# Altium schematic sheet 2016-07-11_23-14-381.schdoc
size 344 x 125 mm; SheetNumber: 1; SheetTotal: 1
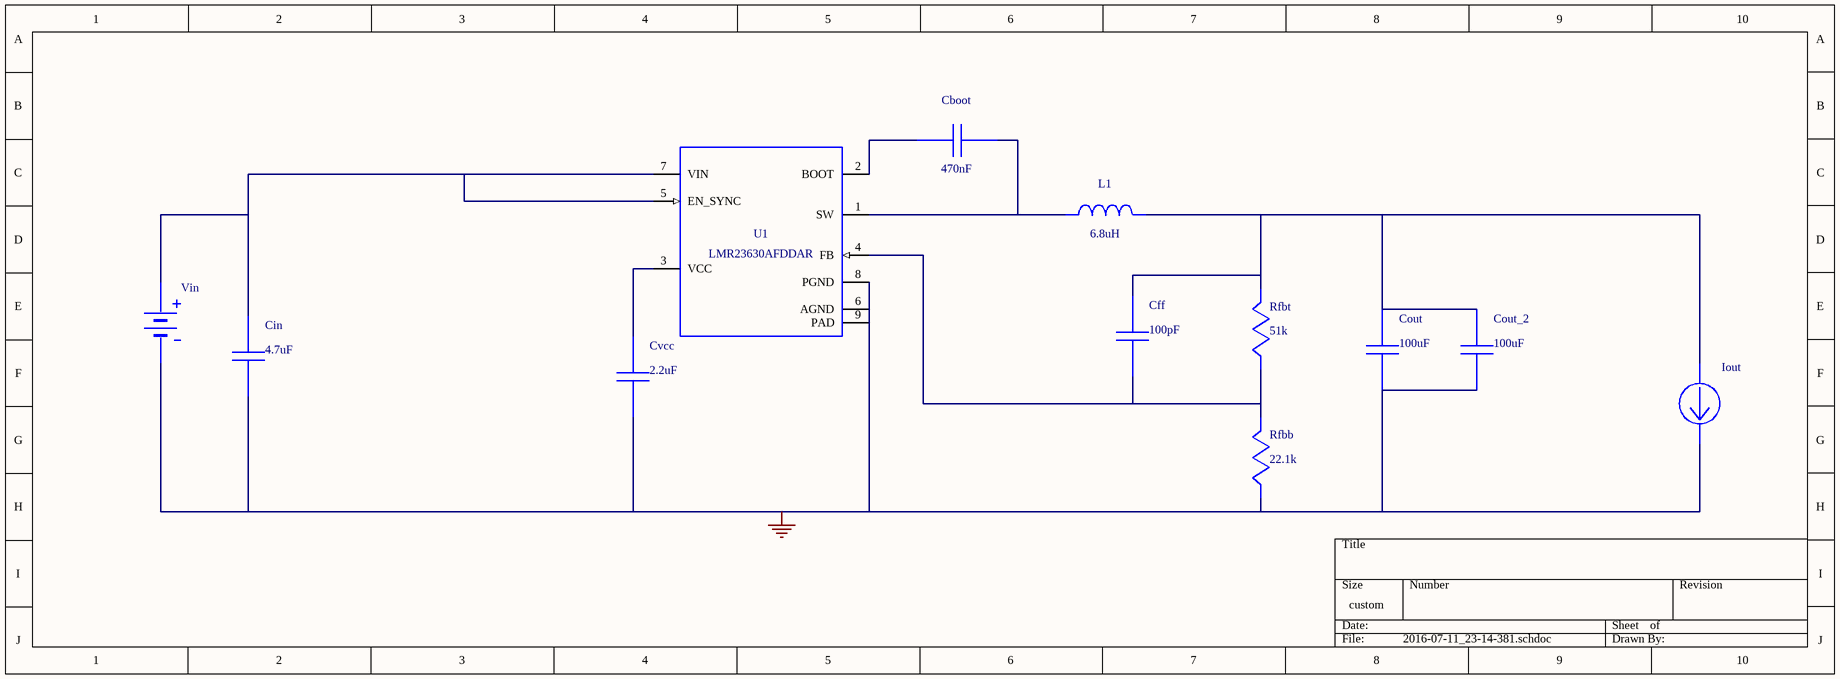
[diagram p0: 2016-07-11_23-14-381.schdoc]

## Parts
Cboot  value 470nF  (hidden comment: GRM21BR71H474KA88L)
Cff  value 100pF  (hidden comment: C0603C101J3GACTU)
Cin  value 4.7uF  (hidden comment: GRM31CR71H475KA12L)
Cout  value 100uF  (hidden comment: GRM31CR60J107ME39L)
Cout_2  value 100uF  (hidden comment: GRM31CR60J107ME39L)
Cvcc  value 2.2uF  (hidden comment: GRM188R60J225KE19D)
Iout  WB_CURRENT_LOAD  (value not drawn)
L1  value 6.8uH  (hidden comment: SRP6540-6R8M)
Rfbb  value 22.1k  (hidden comment: ERJ-6ENF2212V)
Rfbt  value 51k  (hidden comment: RC0603FR-0751KL)
U1  LMR23630AFDDAR
Vin  WB_BATTERY  (value not drawn)

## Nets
0: Cin.2 Cout.2 Cout_2.2 Cvcc.2 Iout.2(-) Rfbb.2 U1.6(AGND) U1.8(PGND) U1.9(PAD) Vin.2(-)
NetCboot_1: Cboot.1 U1.2(BOOT)
NetCboot_2: Cboot.2 L1.1 U1.1(SW)
NetCff_1: Cff.1 Cout.1 Cout_2.1 Iout.1(+) L1.2 Rfbt.1
NetCff_2: Cff.2 Rfbb.1 Rfbt.2 U1.4(FB)
NetCin_1: Cin.1 U1.5(EN_SYNC) U1.7(VIN) Vin.1(+)
NetCvcc_1: Cvcc.1 U1.3(VCC)

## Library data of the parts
Cboot = GRM21BR71H474KA88L: GRM21BR71H474KA8; Manufacturer Name: MuRata
Cff = C0603C101J3GACTU: Manufacturer Name: Kemet
Cin = GRM31CR71H475KA12L: GRM31CR71H475KA1; Manufacturer Name: MuRata
Cout Cout_2 = GRM31CR60J107ME39L: GRM31CR60J107ME3; Manufacturer Name: MuRata
Cvcc = GRM188R60J225KE19D: GRM188R60J225KE1; Manufacturer Name: MuRata
L1 = SRP6540-6R8M: Unknown; Manufacturer Name: Bourns
Rfbb = ERJ-6ENF2212V: Manufacturer Name: Panasonic
Rfbt = RC0603FR-0751KL: Manufacturer Name: Yageo America
U1 = LMR23630AFDDAR: Manufacturer Name: Texas Instruments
